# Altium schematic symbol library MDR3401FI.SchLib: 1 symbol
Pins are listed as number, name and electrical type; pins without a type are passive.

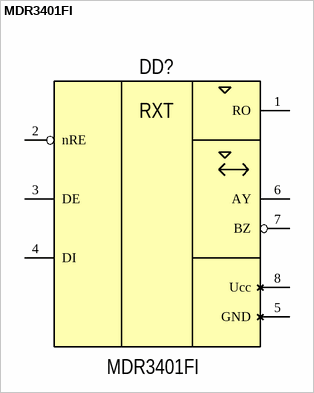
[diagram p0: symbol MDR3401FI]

## MDR3401FI
designator DD?
Микросхема приемопередатчика по стандарту RS-485/422
pins: 1 RO, 2 nRE, 3 DE, 4 DI, 5 GND, 6 AY, 7 BZ, 8 Ucc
